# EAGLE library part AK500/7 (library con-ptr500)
CONNECTOR
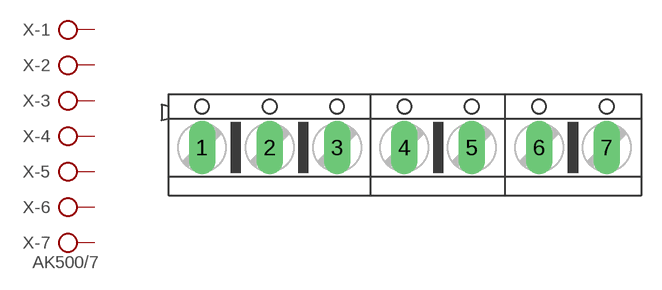
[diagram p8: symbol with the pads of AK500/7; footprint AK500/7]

Designator prefix X; gates -1=KL -2=KL -3=KL -4=KL -5=KL -6=KL -7=KLV

## AK500/7 (OC_FARNELL: unknown; OC_NEWARK: unknown)  [AK500/7]
1  -1:KL  pas
2  -2:KL  pas
3  -3:KL  pas
4  -4:KL  pas
5  -5:KL  pas
6  -6:KL  pas
7  -7:KL  pas

## Footprint AK500/7 (pad centres in mm)
CONNECTOR
drill 1.321 long: 1 -15.037,0; 2 -10.008,0; 3 -5.004,0; 4 0,0; 5 5.004,0; 6 10.008,0; 7 15.037,0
